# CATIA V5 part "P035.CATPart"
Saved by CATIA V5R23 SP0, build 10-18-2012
Part number: P035
Definition: Levier avant
Bounding box of the stored display mesh (mm): x 17 to 27, y -58.588 to 251.846, z 3.465 to 270.597
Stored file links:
  C:\wamp\www\COURS\CONCEPTION GMP1\TITRE 02-SEMESTRE 2\03-TP7-PRESSE MECANIQUE\eleve\P035.CATPart
  C:\Program Files\Dassault Systemes\B11\intel_a\reffiles\standard\MetricThickPitch.txt
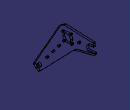
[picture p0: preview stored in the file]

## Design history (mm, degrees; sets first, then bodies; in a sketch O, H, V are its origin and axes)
Set1
  DatumCurve1 to DatumCurve5
  DatumPoint1
  DatumCurve6
  DatumCurve7
  DatumPoint2
  DatumCurve8
  Extract1: ExtractElem edge [face of Pad1 | face of Pad1]
Body1 (main body)
  Sketch1 on yz-plane, origin (0, 0, 0), H (0, 1, 0), V (0, 0, 1)
    point P1 (-60.0733, 22.5508)
    line L1 (-60.0733, 22.5508) -> (72.649, 255.4427)
    line L2 (96.2706, 270.5968) -> (245.049, 264.5733)
    point P2 (245.049, 264.5733)
    line L3 (245.049, 264.5733) -> (247.4563, 247.7446)
    point P3 (252.1294, 215.0772)
    line L4 (252.1294, 215.0772) -> (145.9429, 185.2421)
    point P4 (145.9429, 185.2421)
    line L5 (145.9429, 185.2421) -> (-31.8479, 1.3901)
    point P5 (-31.8479, 1.3901)
    line L6 (-31.8479, 1.3901) -> (-60.0733, 22.5508)
    reference projected line E1 (-33.9636, 27.9727) -> (110, 220) from face of DatumCurve1
    reference projected line E2 (110, 220) -> (230, 237.1661) from face of DatumCurve2
    reference projected circle E3 centre (-33.9636, 27.9727) radius 20 from face of DatumCurve3
    reference projected circle E4 centre (-33.9636, 27.9727) radius 20 from face of DatumCurve4
    reference projected circle E5 centre (-33.9636, 27.9727) radius 20 from face of DatumCurve5
    construction circle A1 centre (110, 220) radius 50
    reference projected point E6 (110, 220) from vertex of DatumPoint1
    line L7 (247.4563, 247.7446) -> (209.8392, 242.3635)
    line L8 (209.8392, 242.3635) -> (213.2379, 218.6053)
    line L9 (213.2379, 218.6053) -> (250.8549, 223.9865)
    point P10 (250.8549, 223.9865)
    reference projected line E7 (110, 220) -> (230, 237.1661) from face of DatumCurve6
    reference projected line E8 (110, 220) -> (230, 237.1661) from face of DatumCurve7
    line L10 (250.8549, 223.9865) -> (252.1294, 215.0772)
    reference projected point E9 (110, 220) from vertex of DatumPoint2
    circle A2 centre (-33.9636, 27.9727) radius 8.5
    reference projected circle E10 centre (-33.9636, 27.9727) radius 20 from face of DatumCurve8
    circle A3 centre (110, 220) radius 20
    line L11 (72.649, 255.4427) -> (96.2706, 270.5968)
    radius A1 = 50
    length L8 = 24
    distance L7 E8 = 8
    distance P2 P3 = 50
    distance L3 E9 = 140
    radius A2 = 8.5
    radius A3 = 20
    angle L2 L11 = 145
    length L9 = 38
    symmetry: P5 P1 E1, P2 P3 E2
    tangency: L1 E3, L5 E4, L6 E5, L2 A1, L1 A1, L11 A1
    concentricity: A1 E6, A2 E10
    coincidence: P4 A1, P10 L3, L3 L10
    parallelism: L8 L3, L9 L7, L7 E7
  Pad1: profile Sketch1, direction (1, 0, 0), length 27, opposite side length -17
  Chamfer1: length 2, angle 45, on edge [face of Pad1 | face of Pad1] (x2)
  Chamfer2: length 3, angle 45, on edge [face of Pad1 | face of Pad1] (x2)
  Fillet1: radius 5, on edge [face of Pad1 | face of Pad1] (x2)
  Chamfer3: length 2, angle 45, on edge [face of Pad1 | face of Pad1] (x2)
  Sketch2 on face of Pad1, origin (27, 32.0103, 102.9211), H (0, 1, 0), V (0, 0, 1)
    point P1 (-23.9845, -18.9404)
    reference projected line E1 (77.9897, 117.0789) -> (-65.9739, -74.9484) from DatumCurve1
    reference projected point E2 (-65.9739, -74.9484) from axis of face of Pad1
    distance P1 E2 = 70
    coincidence: P1 E1
  Hole1: placed by Sketch2, at (27, 8.0258, 83.9807) direction (-1, 0, 0), diameter 6, through (limit type 3), counterbore diameter 9.5, counterbore depth 6
  Sketch3 on face of Pad1, origin (27, 69.1369, 169.3413), H (0, 1, 0), V (0, 0, 1)
    point P1 (-1.1263, -5.3492)
    reference projected line E1 (40.8631, 50.6587) -> (-103.1005, -141.3686) from DatumCurve1
    reference projected point E2 (-103.1005, -141.3686) from axis of face of Pad1
    distance P1 E2 = 170
    coincidence: P1 E1
  Hole2: placed by Sketch3, at (27, 68.0106, 163.992) direction (-1, 0, 0), diameter 6, through (limit type 3), counterbore diameter 9.5, counterbore depth 6
  Sketch4 on face of Pad1, origin (27, 169.9694, 241.1483), H (0, 1, 0), V (0, 0, 1)
    point P1 (-0.5741, -12.6517)
    reference projected point E1 (-59.9694, -21.1483) from axis of face of Pad1
    reference projected line E2 (60.0306, -3.9822) -> (-59.9694, -21.1483) from DatumCurve2
    distance P1 E1 = 60
    coincidence: P1 E2
  Hole3: placed by Sketch4, at (27, 169.3954, 228.4965) direction (-1, 0, 0), diameter 6, through (limit type 3), counterbore diameter 9.5, counterbore depth 6
  Sketch5 on face of Pad1, origin (27, 121.9478, 249.7561), H (0, 1, 0), V (0, 0, 1)
    point P1 (4.848, -7.3529)
    reference projected line E1 (-11.9478, -29.7561) -> (-155.9114, -221.7834) from DatumCurve1
    reference projected point E2 (-11.9478, -29.7561) from axis of face of Pad1
    distance P1 E2 = 28
    coincidence: P1 E1
  Hole4: placed by Sketch5, at (27, 126.7958, 242.4032) direction (-1, 0, 0), diameter 6, through (limit type 3), counterbore diameter 9.5, counterbore depth 6
  CircPattern1: of Hole4, instances 4, angular step 90, axis from face of Pad1
  Sketch6 on face of Pad1, origin (24.7306, -53.9175, 17.9358), H (1, 0, 0), V (0, -0.8001, 0.5998)
    point P1 (-2.7306, -9.9448)
    reference projected line E1 (-7.7306, 7.6936) -> (-7.7306, -27.5831) from edge [face of Pad1 | face of Pad1]
    reference projected line E2 through (0, -9.9448) direction (1, 0) from axis of face of Pad1
    distance P1 E1 = 5
    coincidence: P1 E2
  Hole5: placed by Sketch6, at (22, -45.9606, 11.9704) direction (0, 0.5998, 0.8001), diameter 3.242, through (limit type 6), threaded "M4", thread diameter 4, thread depth 10, pitch 0.7
  Sketch7 on face of Pad1, origin (27, 35.4992, 127.4798), H (0, 1, 0), V (0, 0, 1)
    point P1 (2.5189, -3.4934)
    construction line L1 (37.0165, 42.5214) -> (-21.89, -36.0515)
    reference projected point E1 (32.5114, 36.5123) from axis of face of Hole2
    reference projected point E2 (-27.4735, -43.4991) from axis of face of Hole1
    construction line L2 (-42.2927, 30.102) -> (49.64, -38.8202)
    reference projected point E3 (32.5114, 36.5123) from axis of face of Hole2
    reference projected point E4 (-27.4735, -43.4991) from axis of face of Hole1
    coincidence: E1 L1, L1 E2, P1 L1, P1 L2
    symmetry: E3 E4 L2
  Hole6: placed by Sketch7, at (27, 38.0182, 123.9864) direction (-1, 0, 0), diameter 8, through (limit type 6)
